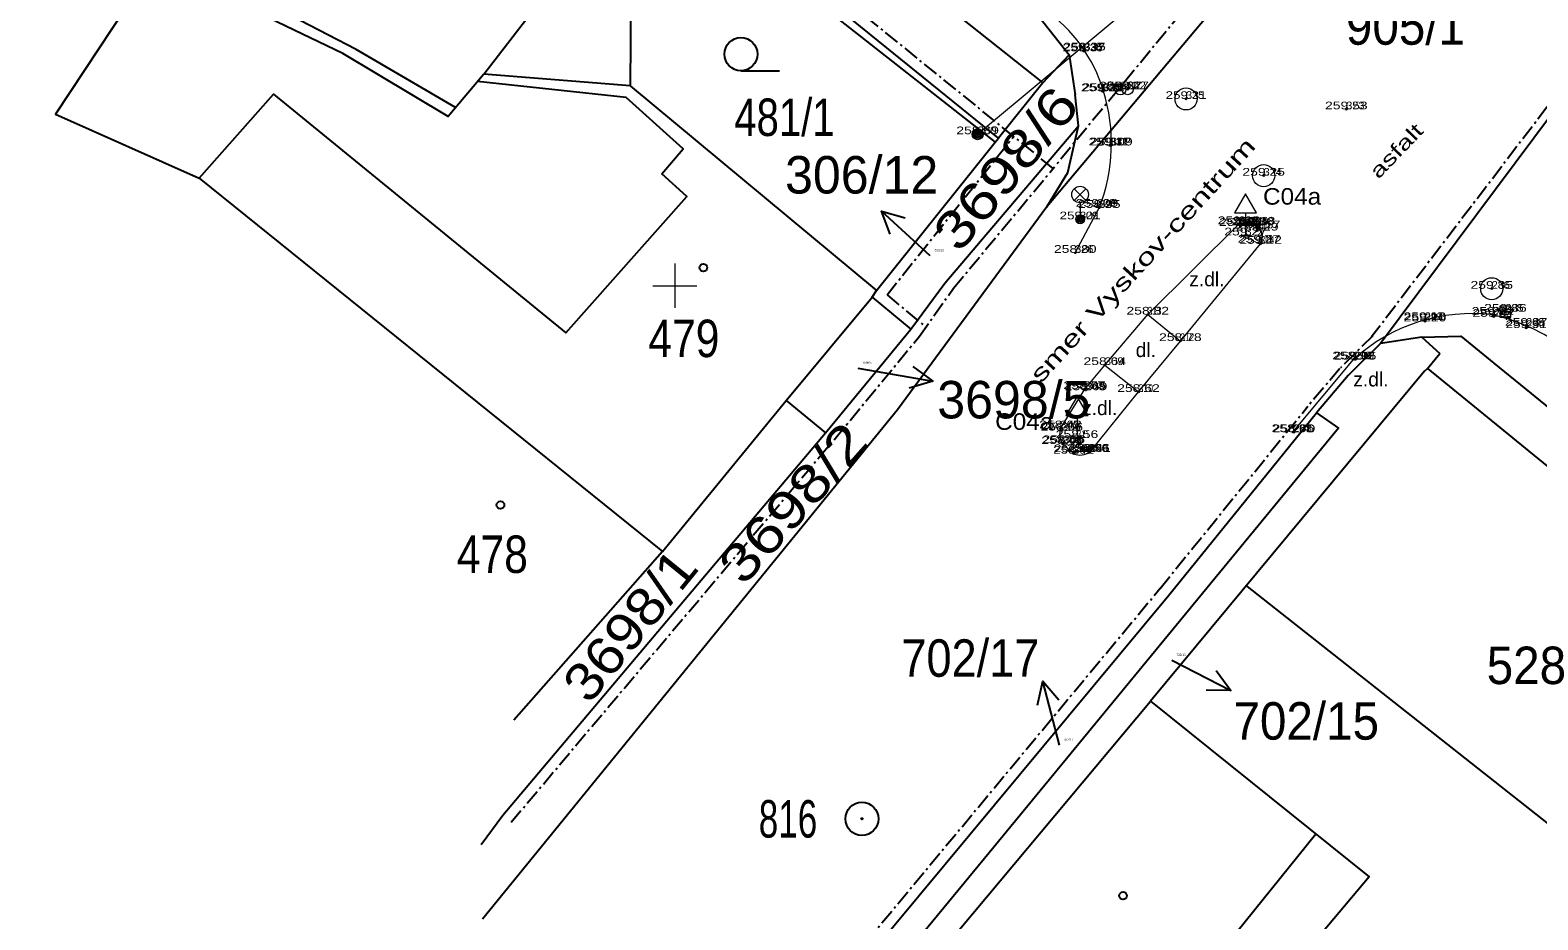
# Model space of a CAD drawing. Extents: x -568530 to -568223, y -1154101 to -1153740.
# Drawn here: x -568529.2 to -568460.8, y -1154028.8 to -1153988.4 of the extents above; entities that cross this region are included whole.
import ezdxf
from ezdxf.enums import TextEntityAlignment as Align

# ---------------------------------------------------------------- set-up
doc = ezdxf.new("R2010")
doc.units = 0
doc.header["$LTSCALE"] = 0.14
doc.header["$PDMODE"] = 32
doc.header["$PDSIZE"] = 0.07
doc.linetypes.add('DOT_DASHED', pattern=[7.7, 5, -1.2, 0.3, -1.2])
for name, color, linetype, lineweight in [('1', 7, 'Continuous', 25), ('10', 7, 'Continuous', 13), ('11', 7, 'Continuous', 13), ('12', 7, 'Continuous', 13), ('16', 7, 'Continuous', 25), ('17', 7, 'Continuous', 13), ('25', 7, 'Continuous', 13), ('27', 7, 'Continuous', 13), ('28', 7, 'Continuous', 13), ('33', 7, 'Continuous', 13), ('34', 7, 'Continuous', 13), ('4', 7, 'Continuous', 25), ('42', 7, 'Continuous', 13), ('51', 7, 'Continuous', 13), ('6', 7, 'DOT_DASHED', 25), ('61', 7, 'Continuous', 13)]:
    doc.layers.add(name, color=color, linetype=linetype, lineweight=lineweight)
for name, color, linetype in [('13', 7, 'Continuous'), ('18', 7, 'Continuous'), ('19', 7, 'Continuous'), ('20', 7, 'Continuous'), ('40', 7, 'Continuous')]:
    doc.layers.add(name, color=color, linetype=linetype)

msp = doc.modelspace()

# ---------------------------------------------------------------- linework, layer by layer
at = {"layer": '1'}
for p, q in [((-568458.68, -1153990.17), (-568467.98, -1154002.62)), ((-568502.03, -1153990.93), (-568490.85, -1154000.22)), ((-568491.05, -1154000.52), (-568489.29, -1154001.97)), ((-568466.1, -1154002.33), (-568465.28, -1154003.07)), ((-568465.85, -1154003.75), (-568438.98, -1154025.71)), ((-568465.98, -1154003.88), (-568478.42, -1154018.84)), ((-568494.94, -1154005.21), (-568493.16, -1154006.67)), ((-568500.56, -1154012.05), (-568507.31, -1154019.71)), ((-568474.11, -1154013.58), (-568446.48, -1154035.38))]:
    msp.add_line(p, q, dxfattribs=at)
for points in [[(-568483.3, -1153990.8), (-568485.31, -1153993.31), (-568498.53, -1153982.6), (-568509.4, -1153973.73), (-568509.03, -1153973.22), (-568517.48, -1153966.66), (-568517.91, -1153967.26), (-568526.79, -1153960.11), (-568528.72, -1153958.54), (-568526.84, -1153956.18)], [(-568470.49, -1153981.39), (-568474.36, -1153986), (-568480.23, -1153992.99), (-568483.12, -1153996.42), (-568489.9, -1154005.63), (-568508.72, -1154028.73)], [(-568508.67, -1153990.41), (-568510.29, -1153992.32), (-568515.06, -1153989.47), (-568523.58, -1153985.37), (-568528.1, -1153992.22), (-568521.58, -1153995.13), (-568500.56, -1154012.05), (-568494.94, -1154005.21), (-568491.05, -1154000.52)], [(-568502.03, -1153990.93), (-568508.67, -1153990.41), (-568504.41, -1153984.88)], [(-568483.3, -1153990.8), (-568482.11, -1153989.53), (-568481.83, -1153991.34)], [(-568483.12, -1153996.42), (-568482.16, -1153994.87), (-568481.68, -1153992.75), (-568481.83, -1153991.34)], [(-568508.79, -1154025.35), (-568507.81, -1154024.02), (-568493.16, -1154006.67), (-568489.29, -1154001.97), (-568487.75, -1153999.88), (-568481.68, -1153992.75)], [(-568491.05, -1154000.52), (-568490.85, -1154000.22), (-568485.47, -1153993.49), (-568485.31, -1153993.31)], [(-568466.1, -1154002.33), (-568467.98, -1154002.62), (-568469.45, -1154004.08), (-568470.88, -1154005.77), (-568469.89, -1154006.46), (-568485.53, -1154025.47), (-568502.98, -1154046.64)], [(-568465.98, -1154003.88), (-568465.85, -1154003.75), (-568465.28, -1154003.07)], [(-568504.75, -1154046.69), (-568477.59, -1154014.04), (-568470.88, -1154005.77)]]:
    msp.add_lwpolyline(points, dxfattribs=at)
msp.add_lwpolyline([(-568478.42, -1154018.84), (-568468.49, -1154026.81), (-568477.14, -1154037.09), (-568487.09, -1154029.21)], close=True, dxfattribs=at)
at = {"layer": '10'}
for p, q in [((-568481.83, -1153998.51), (-568480.74, -1153996.47)), ((-568478.54, -1154001.31), (-568474.4, -1153997.21)), ((-568473.72, -1153997.23), (-568473.49, -1153997.4)), ((-568477.06, -1154002.51), (-568473.42, -1153998.1)), ((-568480.49, -1154003.6), (-568478.54, -1154001.31)), ((-568478.96, -1154004.82), (-568477.06, -1154002.51)), ((-568471.95, -1154006.64), (-568469.2, -1154003.34)), ((-568481.16, -1154007.54), (-568478.96, -1154004.82)), ((-568482.4, -1154007.18), (-568481.9, -1154007.62))]:
    msp.add_line(p, q, dxfattribs=at)
msp.add_lwpolyline([(-568482.5, -1154006.47), (-568481.4, -1154004.69), (-568480.49, -1154003.6)], dxfattribs=at)
for centre, radius, start, end in [((-568487.1888, -1153993.1519), 6.9283, 16.6224, 54.95079), ((-568488.2162, -1153993.5486), 8.0267, 338.65634, 17.23741), ((-568474.0827, -1153997.9905), 0.8425, 64.50422, 112.12642), ((-568474.0017, -1153997.8047), 0.6524, 333.08275, 38.33843), ((-568463.8152, -1154009.2906), 8.0253, 83.30774, 132.14213), ((-568464.9881, -1154010.2166), 9.1429, 53.8913, 76.66924), ((-568481.7011, -1154006.7195), 0.8369, 162.65405, 213.38014), ((-568481.6028, -1154006.9065), 0.7729, 247.38778, 304.95258)]:
    msp.add_arc(centre, radius, start, end, dxfattribs=at)
at = {"layer": '11'}
for p, q in [((-568478.54, -1154001.31), (-568477.06, -1154002.51)), ((-568480.49, -1154003.6), (-568478.96, -1154004.82))]:
    msp.add_line(p, q, dxfattribs=at)
for p in [(-568481.44, -1153989.37), (-568481.41, -1153989.33), (-568480.6, -1153991.18), (-568480.55, -1153991.17), (-568479.78, -1153991.1), (-568479.45, -1153991.09), (-568476.8, -1153991.53), (-568469.53, -1153992), (-568486.26, -1153993.13), (-568480.26, -1153993.64), (-568480.19, -1153993.64), (-568473.28, -1153995.01), (-568481.61, -1153996.99), (-568480.84, -1153996.42), (-568480.74, -1153996.47), (-568474.4, -1153997.21), (-568474.34, -1153997.29), (-568474.1, -1153997.72), (-568473.77, -1153997.26), (-568473.72, -1153997.23), (-568473.57, -1153997.5), (-568473.49, -1153997.4), (-568473.49, -1153998.05), (-568473.42, -1153998.1), (-568481.83, -1153998.51), (-568462.93, -1154000.14), (-568478.54, -1154001.31), (-568465.97, -1154001.56), (-568465.96, -1154001.62), (-568462.88, -1154001.32), (-568462.84, -1154001.41), (-568462.31, -1154001.18), (-568461.37, -1154001.82), (-568477.06, -1154002.51), (-568461.37, -1154001.92), (-568480.49, -1154003.6), (-568469.2, -1154003.34), (-568469.13, -1154003.35), (-568481.4, -1154004.69), (-568481.34, -1154004.74), (-568478.96, -1154004.82), (-568482.5, -1154006.47), (-568482.44, -1154006.57), (-568471.95, -1154006.64), (-568482.4, -1154007.18), (-568482.35, -1154007.14), (-568481.75, -1154006.91), (-568471.91, -1154006.65), (-568481.9, -1154007.62), (-568481.84, -1154007.55), (-568481.23, -1154007.53), (-568481.16, -1154007.54)]:
    msp.add_point(p, dxfattribs=at)
at = {"layer": '16'}
msp.add_line((-568491.69, -1154003.74), (-568491.25, -1154003.82), dxfattribs=at)
at = {"layer": '25', "lineweight": 25}
for p, q in [((-568497, -1153990.25), (-568495.25, -1153990.25)), ((-568488.41, -1153998.64), (-568490.628, -1153996.621)), ((-568491.25, -1154003.82), (-568488.294, -1154004.33)), ((-568477.44, -1154016.99), (-568474.772, -1154018.361)), ((-568482.55, -1154020.84), (-568483.306, -1154017.937))]:
    msp.add_line(p, q, dxfattribs=at)
for points in [[(-568490.225, -1153997.664), (-568490.628, -1153996.621), (-568489.552, -1153996.925)], [(-568489.195, -1154003.668), (-568488.294, -1154004.33), (-568489.365, -1154004.653)], [(-568475.433, -1154017.459), (-568474.772, -1154018.361), (-568475.89, -1154018.348)], [(-568483.537, -1154019.031), (-568483.306, -1154017.937), (-568482.57, -1154018.779)]]:
    msp.add_lwpolyline(points, dxfattribs=at)
for centre, radius in [((-568497, -1153989.5), 0.75), ((-568498.7, -1153999.18), 0.175), ((-568507.91, -1154009.95), 0.175), ((-568491.51, -1154024.18), 0.75), ((-568491.51, -1154024.18), 0.032), ((-568479.66, -1154027.67), 0.175)]:
    msp.add_circle(centre, radius, dxfattribs=at)
at = {"layer": '25'}
for radius in [0.25, 0.2, 0.15, 0.1, 0.05]:
    msp.add_circle((-568486.26, -1153993.13), radius, dxfattribs=at)
at = {"layer": '27'}
msp.add_line((-568462.56, -1154001.18), (-568462.06, -1154001.18), dxfattribs=at)
msp.add_lwpolyline([(-568462.56, -1154001.43), (-568462.06, -1154001.43), (-568462.06, -1154000.93), (-568462.56, -1154000.93)], close=True, dxfattribs=at)
for centre in [(-568476.8, -1153991.53), (-568473.28, -1153995.01), (-568462.93, -1154000.14)]:
    msp.add_circle(centre, 0.5, dxfattribs=at)
at = {"layer": '28'}
for centre in [(-568479.78, -1153991.1), (-568479.45, -1153991.09)]:
    msp.add_circle(centre, 0.25, dxfattribs=at)
at = {"layer": '33'}
for p, q in [((-568481.875, -1153996.13), (-568481.345, -1153995.6)), ((-568481.875, -1153995.6), (-568481.345, -1153996.13)), ((-568481.61, -1153996.24), (-568481.61, -1153996.99))]:
    msp.add_line(p, q, dxfattribs=at)
for centre, radius in [((-568481.61, -1153995.865), 0.375), ((-568481.61, -1153996.99), 0.2), ((-568481.61, -1153996.99), 0.1445), ((-568481.61, -1153996.99), 0.0876)]:
    msp.add_circle(centre, radius, dxfattribs=at)
at = {"layer": '34'}
for p, q in [((-568474.1, -1153996.702), (-568474.1, -1153997.72)), ((-568474.35, -1153997.72), (-568473.85, -1153997.72)), ((-568481.75, -1154005.892), (-568481.75, -1154006.91)), ((-568482, -1154006.91), (-568481.5, -1154006.91))]:
    msp.add_line(p, q, dxfattribs=at)
for points in [[(-568474.6, -1153996.702), (-568473.6, -1153996.702), (-568474.1, -1153995.836)], [(-568482.25, -1154005.892), (-568481.25, -1154005.892), (-568481.75, -1154005.026)]]:
    msp.add_lwpolyline(points, close=True, dxfattribs=at)
at = {"layer": '4'}
for p, q in [((-568526.84, -1153956.18), (-568483.3, -1153990.8)), ((-568498.78, -1153983.02), (-568485.47, -1153993.49)), ((-568484.44, -1153986.56), (-568482.11, -1153989.53)), ((-568501.99, -1153986.8), (-568502.03, -1153990.93)), ((-568462.84, -1154003.52), (-568435.6, -1154025.6)), ((-568479.36, -1154035.33), (-568470.92, -1154024.86))]:
    msp.add_line(p, q, dxfattribs=at)
for points in [[(-568509.95, -1153991.92), (-568514.46, -1153989.29), (-568519.54, -1153986.64), (-568529.25, -1153982.11), (-568523.19, -1153974.46), (-568514.92, -1153980.82)], [(-568521.58, -1153995.13), (-568518.21, -1153991.31), (-568504.95, -1154002.14), (-568499.46, -1153995.95), (-568500.59, -1153994.92), (-568499.62, -1153993.79), (-568502.21, -1153991.47), (-568508.95, -1153990.74)], [(-568466.1, -1154002.33), (-568464.33, -1154002.29), (-568462.84, -1154003.52)]]:
    msp.add_lwpolyline(points, dxfattribs=at)
at = {"layer": '51'}
msp.add_lwpolyline([(-568486.26, -1153993.13), (-568470.55, -1153980.04), (-568452.49, -1153957.53), (-568437.543, -1153968.589)], dxfattribs=at)
at = {"layer": '6'}
for p, q in [((-568482.83, -1153994.68), (-568498.22, -1153982.21)), ((-568459.03, -1153990.08), (-568468.38, -1154002.32)), ((-568490.37, -1154000.42), (-568484.62, -1153993.22)), ((-568487.35, -1154000.11), (-568482.77, -1153994.61)), ((-568490.37, -1154000.42), (-568488.61, -1154001.88)), ((-568488.9, -1154002.29), (-568487.35, -1154000.11)), ((-568492.77, -1154006.99), (-568488.9, -1154002.29)), ((-568468.33, -1154002.27), (-568469.8, -1154003.73)), ((-568469.83, -1154003.76), (-568471.26, -1154005.45)), ((-568477.98, -1154013.73), (-568471.27, -1154005.46)), ((-568507.43, -1154024.34), (-568492.78, -1154006.99)), ((-568505.13, -1154046.37), (-568477.97, -1154013.72))]:
    msp.add_line(p, q, dxfattribs=at)
msp.add_lwpolyline([(-568470.91, -1153980.18), (-568473.37, -1153983.21), (-568482.77, -1153994.61)], dxfattribs=at)
at = {"layer": '61'}
for p, q in [((-568500, -1153999), (-568500, -1154001)), ((-568500, -1153999), (-568500, -1154001)), ((-568501, -1154000), (-568499, -1154000)), ((-568501, -1154000), (-568499, -1154000))]:
    msp.add_line(p, q, dxfattribs=at)

# ---------------------------------------------------------------- texts
at = {"layer": '12'}
for s, width, p in [('259.37', 1.35, (-568481.44, -1153989.37)), ('259.35', 1.35, (-568481.4105, -1153989.33)), ('259.25', 1.35, (-568480.6005, -1153991.18)), ('259.22', 1.35, (-568480.55, -1153991.17)), ('259.27', 1.35, (-568479.78, -1153991.1)), ('259.27', 1.35, (-568479.45, -1153991.09)), ('259.31', 1.3, (-568476.8, -1153991.53)), ('259.53', 1.35, (-568469.53, -1153992)), ('258.69', 1.35, (-568486.26, -1153993.13)), ('259.12', 1.35, (-568480.26, -1153993.64)), ('259.09', 1.35, (-568480.19, -1153993.64)), ('259.25', 1.35, (-568473.2805, -1153995.01)), ('259.09', 1.35, (-568480.84, -1153996.42)), ('258.95', 1.35, (-568480.7405, -1153996.47)), ('259.01', 1.3, (-568481.61, -1153996.99)), ('259.16', 1.35, (-568474.4, -1153997.21)), ('259.30', 1.35, (-568474.3395, -1153997.29)), ('259.30', 1.35, (-568473.7695, -1153997.26)), ('259.18', 1.35, (-568473.72, -1153997.23)), ('259.27', 1.35, (-568474.1, -1153997.72)), ('259.29', 1.35, (-568473.57, -1153997.5)), ('259.17', 1.35, (-568473.49, -1153997.4)), ('259.27', 1.35, (-568473.49, -1153998.05)), ('258.80', 1.35, (-568481.8295, -1153998.51)), ('259.12', 1.35, (-568473.42, -1153998.1)), ('259.35', 1.35, (-568462.9305, -1154000.14)), ('258.82', 1.35, (-568478.54, -1154001.31)), ('259.32', 1.35, (-568462.88, -1154001.32)), ('259.47', 1.35, (-568462.84, -1154001.41)), ('259.36', 1.35, (-568462.31, -1154001.18)), ('259.18', 1.35, (-568465.97, -1154001.56)), ('259.20', 1.35, (-568465.9595, -1154001.62)), ('259.37', 1.35, (-568461.37, -1154001.82)), ('259.51', 1.3, (-568461.37, -1154001.92)), ('258.78', 1.35, (-568477.06, -1154002.51)), ('258.92', 1.35, (-568469.2, -1154003.34)), ('259.05', 1.35, (-568469.1305, -1154003.35)), ('258.64', 1.35, (-568480.49, -1154003.6)), ('258.55', 1.35, (-568481.4005, -1154004.69)), ('258.69', 1.35, (-568481.34, -1154004.74)), ('258.62', 1.35, (-568478.96, -1154004.82)), ('258.43', 1.35, (-568482.5, -1154006.47)), ('258.56', 1.35, (-568482.44, -1154006.57)), ('258.56', 1.35, (-568481.75, -1154006.91)), ('258.66', 1.35, (-568471.95, -1154006.64)), ('258.70', 1.35, (-568471.9095, -1154006.65)), ('258.40', 1.35, (-568482.3995, -1154007.18)), ('258.55', 1.35, (-568482.3505, -1154007.14)), ('258.41', 1.3, (-568481.9, -1154007.62)), ('258.54', 1.35, (-568481.84, -1154007.55)), ('258.56', 1.35, (-568481.23, -1154007.53)), ('258.41', 1.3, (-568481.16, -1154007.54))]:
    msp.add_text(s, height=0.35, dxfattribs=dict(at, width=width)).set_placement(p, align=Align.CENTER)
at = {"layer": '13'}
for s, width, p in [('336', 1.05, (-568481.44, -1153989.37)), ('335', 1.05, (-568481.41, -1153989.33)), ('334', 1.05, (-568480.6, -1153991.18)), ('333', 1.05, (-568480.55, -1153991.17)), ('341', 0.95, (-568479.78, -1153991.1)), ('342', 1.05, (-568479.45, -1153991.09)), ('325', 1.05, (-568476.8, -1153991.53)), ('323', 1.05, (-568469.53, -1153992)), ('330', 1.1, (-568486.26, -1153993.13)), ('332', 1.05, (-568480.26, -1153993.64)), ('331', 0.95, (-568480.19, -1153993.64)), ('324', 1.05, (-568473.28, -1153995.01)), ('328', 1.05, (-568480.84, -1153996.42)), ('327', 1.05, (-568480.74, -1153996.47)), ('329', 1.05, (-568481.61, -1153996.99)), ('320', 1.1, (-568474.4, -1153997.21)), ('321', 0.95, (-568474.34, -1153997.29)), ('319', 0.8, (-568473.77, -1153997.26)), ('318', 0.8, (-568473.72, -1153997.23)), ('322', 1.05, (-568474.1, -1153997.72)), ('317', 0.8, (-568473.57, -1153997.5)), ('316', 0.8, (-568473.49, -1153997.4)), ('315', 0.8, (-568473.49, -1153998.05)), ('326', 1.05, (-568481.83, -1153998.51)), ('314', 0.8, (-568473.42, -1153998.1)), ('286', 1.05, (-568462.93, -1154000.14)), ('313', 0.8, (-568478.54, -1154001.31)), ('291', 0.95, (-568462.88, -1154001.32)), ('292', 1.05, (-568462.84, -1154001.41)), ('285', 1.05, (-568462.31, -1154001.18)), ('293', 1.05, (-568465.97, -1154001.56)), ('294', 1.05, (-568465.96, -1154001.62)), ('289', 1.05, (-568461.37, -1154001.82)), ('290', 1.1, (-568461.37, -1154001.92)), ('312', 0.8, (-568477.06, -1154002.51)), ('295', 1.05, (-568469.2, -1154003.34)), ('296', 1.1, (-568469.13, -1154003.35)), ('309', 1.1, (-568480.49, -1154003.6)), ('307', 1.1, (-568481.4, -1154004.69)), ('308', 1.1, (-568481.34, -1154004.74)), ('310', 0.85, (-568478.96, -1154004.82)), ('305', 1.1, (-568482.5, -1154006.47)), ('306', 1.1, (-568482.44, -1154006.57)), ('311', 0.7, (-568481.75, -1154006.91)), ('297', 1.05, (-568471.95, -1154006.64)), ('298', 1.05, (-568471.91, -1154006.65)), ('303', 1.1, (-568482.4, -1154007.18)), ('304', 1.1, (-568482.35, -1154007.14)), ('302', 1.1, (-568481.84, -1154007.55)), ('300', 1.15, (-568481.23, -1154007.53)), ('299', 1.05, (-568481.16, -1154007.54))]:
    msp.add_text(s, height=0.35, dxfattribs=dict(at, width=width)).set_placement(p)
msp.add_text('301', height=0.35, dxfattribs=at).set_placement((-568481.9, -1154007.62))
at = {"layer": '17', "width": 0.7}
msp.add_text('816', height=1.7, dxfattribs=at).set_placement((-568493.536, -1154025.03), align=Align.RIGHT)
at = {"layer": '18'}
for s, height, width, p in [('481/1', 1.7, 0.8, (-568497.3, -1153993.21)), ('702/15', 0.1, 0.95, (-568477.24, -1154016.79)), ('528', 1.7, 0.95, (-568463.16, -1154018.07)), ('702/15', 1.7, 0.95, (-568474.65, -1154020.59)), ('702/17', 0.1, 0.9, (-568482.35, -1154020.64))]:
    msp.add_text(s, height=height, dxfattribs=dict(at, width=width)).set_placement(p)
for s, rotation, width, p in [('3698/6', 50.4, 1.25, (-568487.096, -1153998.569)), ('3698/2', 48.4, 1.25, (-568496.886, -1154013.668)), ('3698/1', 50.9, 1.15, (-568503.889, -1154019.039))]:
    msp.add_text(s, height=1.7, rotation=rotation, dxfattribs=dict(at, width=width)).set_placement(p)
for height, p in [(0.1, (-568491.49, -1154003.54)), (1.7, (-568488.09, -1154006.02))]:
    msp.add_text('3698/5', height=height, dxfattribs=at).set_placement(p)
at = {"layer": '18', "width": 0.9}
msp.add_text('702/17', height=1.7, dxfattribs=at).set_placement((-568483.459, -1154017.74), align=Align.RIGHT)
at = {"layer": '19', "width": 0.85}
for s, p in [('479', (-568501.2, -1154003.24)), ('478', (-568509.89, -1154013.03))]:
    msp.add_text(s, height=1.7, dxfattribs=at).set_placement(p)
at = {"layer": '20', "width": 0.95}
msp.add_text('905/1', height=1.7, dxfattribs=at).set_placement((-568469.55, -1153989.07))
at = {"layer": '20'}
msp.add_text('306/12', height=1.7, dxfattribs=at).set_placement((-568488.045, -1153995.82), align=Align.RIGHT)
msp.add_text('306/12', height=0.1, dxfattribs=at).set_placement((-568488.21, -1153998.44))
at = {"layer": '40', "width": 1.45}
msp.add_text('asfalt', height=0.65, rotation=46.142, dxfattribs=at).set_placement((-568468.071, -1153995.195))
at = {"layer": '40'}
for s, p in [('z.dl.', (-568476.654, -1154000.026)), ('dl.', (-568479.086, -1154003.237)), ('z.dl.', (-568469.211, -1154004.57)), ('z.dl.', (-568481.517, -1154005.872))]:
    msp.add_text(s, height=0.65, dxfattribs=at).set_placement(p)
at = {"layer": '42', "width": 1.5}
msp.add_text('smer Vyskov-centrum', height=0.75, rotation=47.66, dxfattribs=at).set_placement((-568478.4922, -1153999.0901), align=Align.CENTER)
at = {"layer": '42', "width": 1.1}
for p in [(-568471.9905, -1153996.324), (-568484.1455, -1154006.538)]:
    msp.add_text('C04a', height=0.75, dxfattribs=at).set_placement(p, align=Align.CENTER)

doc.saveas('drawing.dxf')
